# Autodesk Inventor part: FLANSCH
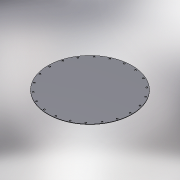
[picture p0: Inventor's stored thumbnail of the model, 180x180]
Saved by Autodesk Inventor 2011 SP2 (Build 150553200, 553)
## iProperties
Created: 2012-02
Part Number: FLANSCH
Material: S235JRG2
Document SubType Name: Modeling
Designer: SCHALLA
Density: 7.85 g/cm^3
Mass: 170460 g
Surface Area: 23373.4 cm^2
Volume: 21714.7 cm^3
MatBom2.0.1.: PS!Inventor!PV!15.0  SP: 1!AVMa!2!AVMi!0!AVBu!0
Author: SCHALLA
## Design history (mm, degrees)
derived "behaelter_multi_body.ipt"
node "Volumenkörper2"
feature "FLANSCH::behaelter_multi_body.ipt" dims "d2" = 10
tag "Bezeichnung1"
